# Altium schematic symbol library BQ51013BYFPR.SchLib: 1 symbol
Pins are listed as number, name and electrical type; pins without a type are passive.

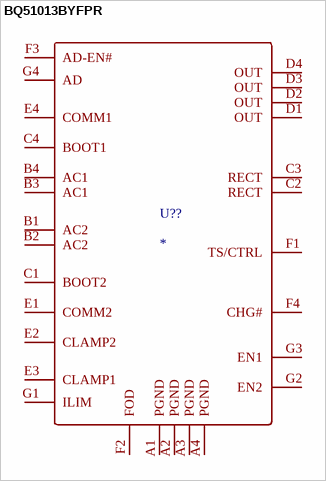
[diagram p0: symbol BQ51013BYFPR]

## BQ51013BYFPR
designator U??
footprint DSBGA-28_L3.0-W1.9-R7-C4-P0.40-BL
pins: A1 PGND, A2 PGND, A3 PGND, A4 PGND, B1 AC2, B2 AC2, B3 AC1, B4 AC1, C1 BOOT2, C2 RECT, C3 RECT, C4 BOOT1, D1 OUT, D2 OUT, D3 OUT, D4 OUT, E1 COMM2, E2 CLAMP2, E3 CLAMP1, E4 COMM1, F1 TS/CTRL, F2 FOD, F3 AD-EN#, F4 CHG#, G1 ILIM, G2 EN2, G3 EN1, G4 AD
